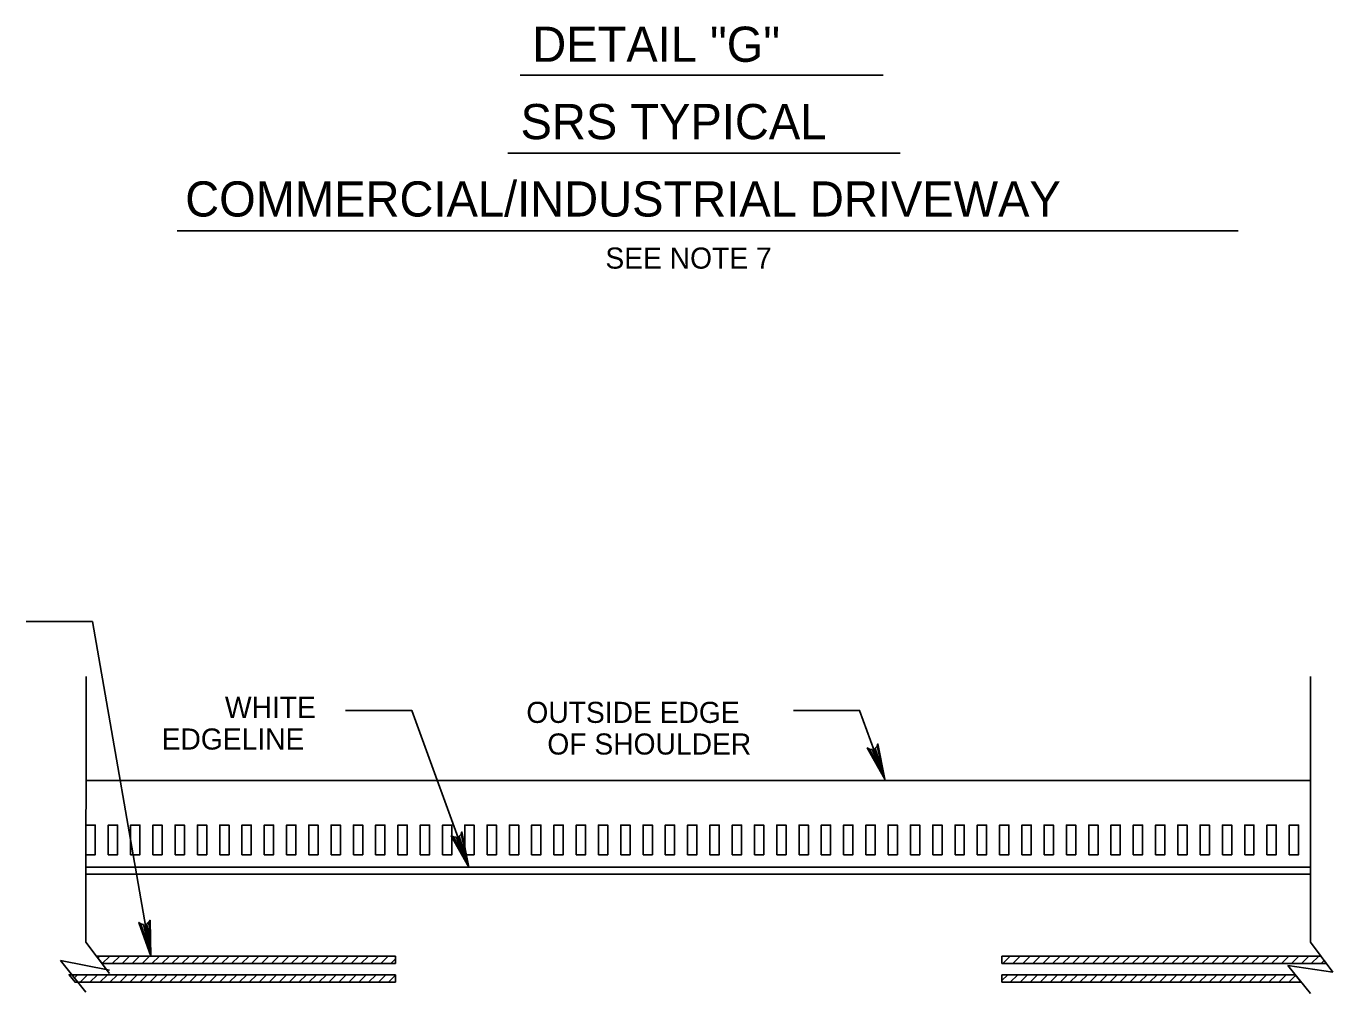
# Model space of a CAD drawing. Extents: x 632008 to 634206, y 294231 to 297795.
# Drawn here: x 632382 to 632567.7, y 296762.1 to 296899.6 of the extents above; entities that cross this region are included whole.
import ezdxf

# ---------------------------------------------------------------- set-up
doc = ezdxf.new("R2010")
doc.units = 0
doc.layers.add('1', color=7, linetype='Continuous')
doc.layers.add('Level 2', color=7, linetype='Continuous')

msp = doc.modelspace()

# ---------------------------------------------------------------- linework, layer by layer
at = {"layer": '1'}
for p, q in [((632452.22, 296892.58), (632503.82, 296892.58)), ((632450.48, 296881.51), (632506.24, 296881.51)), ((632403.47, 296870.45), (632554.25, 296870.45)), ((632392.2, 296767.04), (632392.47, 296767.31)), ((632392.82, 296766.25), (632393.88, 296767.31)), ((632394.24, 296766.25), (632395.3, 296767.31)), ((632395.65, 296766.25), (632396.71, 296767.31)), ((632397.07, 296766.25), (632398.12, 296767.31)), ((632398.48, 296766.25), (632399.54, 296767.31)), ((632399.89, 296766.25), (632400.95, 296767.31)), ((632401.31, 296766.25), (632402.37, 296767.31)), ((632402.72, 296766.25), (632403.78, 296767.31)), ((632404.14, 296766.25), (632405.2, 296767.31)), ((632405.55, 296766.25), (632406.61, 296767.31)), ((632406.97, 296766.25), (632408.02, 296767.31)), ((632408.38, 296766.25), (632409.44, 296767.31)), ((632409.79, 296766.25), (632410.85, 296767.31)), ((632411.21, 296766.25), (632412.27, 296767.31)), ((632412.62, 296766.25), (632413.68, 296767.31)), ((632414.04, 296766.25), (632415.09, 296767.31)), ((632415.45, 296766.25), (632416.51, 296767.31)), ((632416.87, 296766.25), (632417.92, 296767.31)), ((632418.28, 296766.25), (632419.34, 296767.31)), ((632419.69, 296766.25), (632420.75, 296767.31)), ((632421.11, 296766.25), (632422.17, 296767.31)), ((632422.52, 296766.25), (632423.58, 296767.31)), ((632423.94, 296766.25), (632424.99, 296767.31)), ((632425.35, 296766.25), (632426.41, 296767.31)), ((632426.76, 296766.25), (632427.82, 296767.31)), ((632428.18, 296766.25), (632429.24, 296767.31)), ((632429.59, 296766.25), (632430.65, 296767.31)), ((632431.01, 296766.25), (632432.07, 296767.31)), ((632432.42, 296766.25), (632433.48, 296767.31)), ((632433.84, 296766.25), (632434.51, 296766.93)), ((632434.51, 296766.25), (632434.51, 296767.31)), ((632520.67, 296766.25), (632520.67, 296767.31)), ((632520.82, 296766.25), (632521.88, 296767.31)), ((632522.24, 296766.25), (632523.3, 296767.31)), ((632523.65, 296766.25), (632524.71, 296767.31)), ((632525.06, 296766.25), (632526.12, 296767.31)), ((632526.48, 296766.25), (632527.54, 296767.31)), ((632527.89, 296766.25), (632528.95, 296767.31)), ((632529.31, 296766.25), (632530.37, 296767.31)), ((632530.72, 296766.25), (632531.78, 296767.31)), ((632532.14, 296766.25), (632533.2, 296767.31)), ((632533.55, 296766.25), (632534.61, 296767.31)), ((632534.96, 296766.25), (632536.02, 296767.31)), ((632536.38, 296766.25), (632537.44, 296767.31)), ((632537.79, 296766.25), (632538.85, 296767.31)), ((632539.21, 296766.25), (632540.27, 296767.31)), ((632540.62, 296766.25), (632541.68, 296767.31)), ((632542.04, 296766.25), (632543.1, 296767.31)), ((632543.45, 296766.25), (632544.51, 296767.31)), ((632544.86, 296766.25), (632545.92, 296767.31)), ((632546.28, 296766.25), (632547.34, 296767.31)), ((632547.69, 296766.25), (632548.75, 296767.31)), ((632549.11, 296766.25), (632550.17, 296767.31)), ((632550.52, 296766.25), (632551.58, 296767.31)), ((632551.93, 296766.25), (632553, 296767.31)), ((632553.35, 296766.25), (632554.41, 296767.31)), ((632554.76, 296766.25), (632555.82, 296767.31)), ((632556.18, 296766.25), (632557.24, 296767.31)), ((632557.59, 296766.25), (632558.65, 296767.31)), ((632559.01, 296766.25), (632560.07, 296767.31)), ((632560.42, 296766.25), (632561.48, 296767.31)), ((632561.83, 296766.25), (632562.89, 296767.31)), ((632563.25, 296766.25), (632564.31, 296767.31)), ((632564.66, 296766.25), (632565.72, 296767.31)), ((632566.08, 296766.25), (632566.5, 296766.67)), ((632388.86, 296764.21), (632389.31, 296764.67)), ((632389.67, 296763.61), (632390.73, 296764.67)), ((632391.08, 296763.61), (632392.14, 296764.67)), ((632392.5, 296763.61), (632393.56, 296764.67)), ((632393.91, 296763.61), (632394.97, 296764.67)), ((632395.33, 296763.61), (632396.38, 296764.67)), ((632396.74, 296763.61), (632397.8, 296764.67)), ((632398.16, 296763.61), (632399.21, 296764.67)), ((632399.57, 296763.61), (632400.63, 296764.67)), ((632400.98, 296763.61), (632402.04, 296764.67)), ((632402.4, 296763.61), (632403.46, 296764.67)), ((632403.81, 296763.61), (632404.87, 296764.67)), ((632405.23, 296763.61), (632406.28, 296764.67)), ((632406.64, 296763.61), (632407.7, 296764.67)), ((632408.05, 296763.61), (632409.11, 296764.67)), ((632409.47, 296763.61), (632410.53, 296764.67)), ((632410.88, 296763.61), (632411.94, 296764.67)), ((632412.3, 296763.61), (632413.35, 296764.67)), ((632413.71, 296763.61), (632414.77, 296764.67)), ((632415.13, 296763.61), (632416.18, 296764.67)), ((632416.54, 296763.61), (632417.6, 296764.67)), ((632417.95, 296763.61), (632419.01, 296764.67)), ((632419.37, 296763.61), (632420.43, 296764.67)), ((632420.78, 296763.61), (632421.84, 296764.67)), ((632422.2, 296763.61), (632423.25, 296764.67)), ((632423.61, 296763.61), (632424.67, 296764.67)), ((632425.03, 296763.61), (632426.08, 296764.67)), ((632426.44, 296763.61), (632427.5, 296764.67)), ((632427.85, 296763.61), (632428.91, 296764.67)), ((632429.27, 296763.61), (632430.33, 296764.67)), ((632430.68, 296763.61), (632431.74, 296764.67)), ((632432.1, 296763.61), (632433.15, 296764.67)), ((632434.51, 296763.61), (632434.51, 296764.67)), ((632520.67, 296763.61), (632520.67, 296764.67)), ((632520.67, 296763.83), (632521.52, 296764.67)), ((632521.87, 296763.61), (632522.93, 296764.67)), ((632523.29, 296763.61), (632524.34, 296764.67)), ((632524.7, 296763.61), (632525.76, 296764.67)), ((632526.12, 296763.61), (632527.17, 296764.67)), ((632527.53, 296763.61), (632528.59, 296764.67)), ((632528.95, 296763.61), (632530, 296764.67)), ((632530.36, 296763.61), (632531.42, 296764.67)), ((632531.77, 296763.61), (632532.83, 296764.67)), ((632533.19, 296763.61), (632534.24, 296764.67)), ((632534.6, 296763.61), (632535.66, 296764.67)), ((632536.02, 296763.61), (632537.07, 296764.67)), ((632537.43, 296763.61), (632538.49, 296764.67)), ((632538.85, 296763.61), (632539.9, 296764.67)), ((632540.26, 296763.61), (632541.32, 296764.67)), ((632541.67, 296763.61), (632542.73, 296764.67)), ((632543.09, 296763.61), (632544.14, 296764.67)), ((632544.5, 296763.61), (632545.56, 296764.67)), ((632545.92, 296763.61), (632546.97, 296764.67)), ((632547.33, 296763.61), (632548.39, 296764.67)), ((632548.74, 296763.61), (632549.8, 296764.67)), ((632550.16, 296763.61), (632551.21, 296764.67)), ((632551.57, 296763.61), (632552.63, 296764.67)), ((632552.99, 296763.61), (632554.04, 296764.67)), ((632554.4, 296763.61), (632555.46, 296764.67)), ((632555.82, 296763.61), (632556.87, 296764.67)), ((632557.23, 296763.61), (632558.29, 296764.67)), ((632558.64, 296763.61), (632559.7, 296764.67)), ((632560.06, 296763.61), (632561.11, 296764.67)), ((632433.51, 296763.61), (632434.51, 296764.62)), ((632561.47, 296763.61), (632562.45, 296764.59)), ((632562.89, 296763.61), (632563.08, 296763.81))]:
    msp.add_line(p, q, dxfattribs=at)
for points in [[(632434.51, 296766.25), (632392.79, 296766.25), (632392, 296767.31), (632434.51, 296767.31)], [(632520.67, 296767.31), (632566.02, 296767.31), (632566.81, 296766.25), (632520.67, 296766.25)], [(632434.51, 296763.61), (632388.97, 296763.61), (632388.11, 296764.67), (632434.51, 296764.67)], [(632520.67, 296764.67), (632562.38, 296764.67), (632563.24, 296763.61), (632520.67, 296763.61)]]:
    msp.add_lwpolyline(points, dxfattribs=at)
at = {"layer": 'Level 2'}
for p, q in [((632390.51, 296769.29), (632390.52, 296807.1)), ((632564.54, 296769.29), (632564.54, 296807.1)), ((632564.54, 296792.31), (632390.51, 296792.31)), ((632564.54, 296779.96), (632390.51, 296779.96)), ((632564.54, 296778.95), (632390.51, 296778.95)), ((632393.83, 296764.86), (632390.51, 296769.29)), ((632567.72, 296765.04), (632564.54, 296769.29)), ((632386.87, 296766.67), (632393.83, 296765.32)), ((632390.51, 296762.17), (632386.87, 296766.67)), ((632564.54, 296762.01), (632561.33, 296765.96)), ((632561.33, 296765.96), (632567.72, 296765.04))]:
    msp.add_line(p, q, dxfattribs=at)
for points in [[(632382, 296814.88), (632391.42, 296814.88), (632399.73, 296767.31)], [(632427.39, 296802.26), (632436.8, 296802.26), (632444.91, 296779.96)], [(632491.05, 296802.26), (632500.46, 296802.26), (632504.08, 296792.31)], [(632502.95, 296797.17), (632502.69, 296796.89), (632504.03, 296792.46), (632502.95, 296797.17), (632503.06, 296797.48), (632504.03, 296792.46), (632502.23, 296796.72), (632501.85, 296796.76), (632504.03, 296792.46), (632501.55, 296796.92), (632501.85, 296796.76)], [(632443.84, 296784.67), (632443.57, 296784.39), (632444.91, 296779.96), (632443.84, 296784.67), (632443.95, 296784.98), (632444.91, 296779.96), (632443.12, 296784.22), (632442.74, 296784.26), (632444.91, 296779.96), (632442.43, 296784.43), (632442.74, 296784.26)], [(632399.45, 296772.13), (632399.15, 296771.9), (632399.73, 296767.31), (632399.45, 296772.13), (632399.61, 296772.41), (632399.73, 296767.31), (632398.67, 296771.81), (632398.3, 296771.91), (632399.73, 296767.31), (632398.03, 296772.12), (632398.3, 296771.91)]]:
    msp.add_lwpolyline(points, dxfattribs=at)
for points in [[(632390.51, 296781.74), (632391.83, 296781.74), (632391.83, 296785.96), (632390.51, 296785.96)], [(632393.68, 296781.74), (632395, 296781.74), (632395, 296785.96), (632393.68, 296785.96)], [(632396.85, 296781.74), (632398.17, 296781.74), (632398.17, 296785.96), (632396.85, 296785.96)], [(632400.02, 296781.74), (632401.33, 296781.74), (632401.33, 296785.96), (632400.02, 296785.96)], [(632403.18, 296781.74), (632404.5, 296781.74), (632404.5, 296785.96), (632403.18, 296785.96)], [(632406.35, 296781.74), (632407.67, 296781.74), (632407.67, 296785.96), (632406.35, 296785.96)], [(632409.52, 296781.74), (632410.84, 296781.74), (632410.84, 296785.96), (632409.52, 296785.96)], [(632412.68, 296781.74), (632414, 296781.74), (632414, 296785.96), (632412.68, 296785.96)], [(632415.85, 296781.74), (632417.17, 296781.74), (632417.17, 296785.96), (632415.85, 296785.96)], [(632419.02, 296781.74), (632420.34, 296781.74), (632420.34, 296785.96), (632419.02, 296785.96)], [(632422.18, 296781.74), (632423.5, 296781.74), (632423.5, 296785.96), (632422.18, 296785.96)], [(632425.35, 296781.74), (632426.67, 296781.74), (632426.67, 296785.96), (632425.35, 296785.96)], [(632428.52, 296781.74), (632429.84, 296781.74), (632429.84, 296785.96), (632428.52, 296785.96)], [(632431.68, 296781.74), (632433, 296781.74), (632433, 296785.96), (632431.68, 296785.96)], [(632434.85, 296781.74), (632436.17, 296781.74), (632436.17, 296785.96), (632434.85, 296785.96)], [(632438.02, 296781.74), (632439.34, 296781.74), (632439.34, 296785.96), (632438.02, 296785.96)], [(632441.19, 296781.74), (632442.51, 296781.74), (632442.51, 296785.96), (632441.19, 296785.96)], [(632444.35, 296781.74), (632445.67, 296781.74), (632445.67, 296785.96), (632444.35, 296785.96)], [(632447.52, 296781.74), (632448.84, 296781.74), (632448.84, 296785.96), (632447.52, 296785.96)], [(632450.69, 296781.74), (632452.01, 296781.74), (632452.01, 296785.96), (632450.69, 296785.96)], [(632453.85, 296781.74), (632455.17, 296781.74), (632455.17, 296785.96), (632453.85, 296785.96)], [(632457.02, 296781.74), (632458.34, 296781.74), (632458.34, 296785.96), (632457.02, 296785.96)], [(632460.19, 296781.74), (632461.51, 296781.74), (632461.51, 296785.96), (632460.19, 296785.96)], [(632463.35, 296781.74), (632464.67, 296781.74), (632464.67, 296785.96), (632463.35, 296785.96)], [(632466.52, 296781.74), (632467.84, 296781.74), (632467.84, 296785.96), (632466.52, 296785.96)], [(632469.69, 296781.74), (632471.01, 296781.74), (632471.01, 296785.96), (632469.69, 296785.96)], [(632472.85, 296781.74), (632474.17, 296781.74), (632474.17, 296785.96), (632472.85, 296785.96)], [(632476.02, 296781.74), (632477.34, 296781.74), (632477.34, 296785.96), (632476.02, 296785.96)], [(632479.19, 296781.74), (632480.51, 296781.74), (632480.51, 296785.96), (632479.19, 296785.96)], [(632482.36, 296781.74), (632483.68, 296781.74), (632483.68, 296785.96), (632482.36, 296785.96)], [(632485.52, 296781.74), (632486.84, 296781.74), (632486.84, 296785.96), (632485.52, 296785.96)], [(632488.69, 296781.74), (632490.01, 296781.74), (632490.01, 296785.96), (632488.69, 296785.96)], [(632491.86, 296781.74), (632493.18, 296781.74), (632493.18, 296785.96), (632491.86, 296785.96)], [(632495.02, 296781.74), (632496.34, 296781.74), (632496.34, 296785.96), (632495.02, 296785.96)], [(632498.19, 296781.74), (632499.51, 296781.74), (632499.51, 296785.96), (632498.19, 296785.96)], [(632501.36, 296781.74), (632502.68, 296781.74), (632502.68, 296785.96), (632501.36, 296785.96)], [(632504.52, 296781.74), (632505.84, 296781.74), (632505.84, 296785.96), (632504.52, 296785.96)], [(632507.69, 296781.74), (632509.01, 296781.74), (632509.01, 296785.96), (632507.69, 296785.96)], [(632510.86, 296781.74), (632512.18, 296781.74), (632512.18, 296785.96), (632510.86, 296785.96)], [(632514.02, 296781.74), (632515.34, 296781.74), (632515.34, 296785.96), (632514.02, 296785.96)], [(632517.19, 296781.74), (632518.51, 296781.74), (632518.51, 296785.96), (632517.19, 296785.96)], [(632520.36, 296781.74), (632521.68, 296781.74), (632521.68, 296785.96), (632520.36, 296785.96)], [(632523.53, 296781.74), (632524.85, 296781.74), (632524.85, 296785.96), (632523.53, 296785.96)], [(632526.69, 296781.74), (632528.01, 296781.74), (632528.01, 296785.96), (632526.69, 296785.96)], [(632529.86, 296781.74), (632531.18, 296781.74), (632531.18, 296785.96), (632529.86, 296785.96)], [(632533.03, 296781.74), (632534.35, 296781.74), (632534.35, 296785.96), (632533.03, 296785.96)], [(632536.19, 296781.74), (632537.51, 296781.74), (632537.51, 296785.96), (632536.19, 296785.96)], [(632539.36, 296781.74), (632540.68, 296781.74), (632540.68, 296785.96), (632539.36, 296785.96)], [(632542.53, 296781.74), (632543.85, 296781.74), (632543.85, 296785.96), (632542.53, 296785.96)], [(632545.69, 296781.74), (632547.01, 296781.74), (632547.01, 296785.96), (632545.69, 296785.96)], [(632548.86, 296781.74), (632550.18, 296781.74), (632550.18, 296785.96), (632548.86, 296785.96)], [(632552.03, 296781.74), (632553.35, 296781.74), (632553.35, 296785.96), (632552.03, 296785.96)], [(632555.2, 296781.74), (632556.51, 296781.74), (632556.51, 296785.96), (632555.2, 296785.96)], [(632558.36, 296781.74), (632559.68, 296781.74), (632559.68, 296785.96), (632558.36, 296785.96)], [(632561.53, 296781.74), (632562.85, 296781.74), (632562.85, 296785.96), (632561.53, 296785.96)]]:
    msp.add_lwpolyline(points, close=True, dxfattribs=at)

# ---------------------------------------------------------------- texts
for s, height, p in [('DETAIL "G"', 5, (632453.94, 296894.49)), ('SRS TYPICAL', 5, (632452.27, 296883.49)), ('COMMERCIAL/INDUSTRIAL DRIVEWAY', 5, (632404.61, 296872.49)), ('SEE NOTE 7', 3, (632464.33, 296865.08)), ('WHITE', 3, (632410.26, 296801.19)), ('OUTSIDE EDGE', 3, (632453.1, 296800.48)), ('EDGELINE', 3, (632401.26, 296796.69)), ('OF SHOULDER', 3, (632456.08, 296795.98))]:
    msp.add_text(s, height=height, dxfattribs=at).set_placement(p)

doc.saveas('drawing.dxf')
